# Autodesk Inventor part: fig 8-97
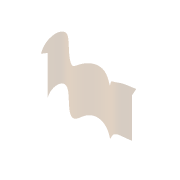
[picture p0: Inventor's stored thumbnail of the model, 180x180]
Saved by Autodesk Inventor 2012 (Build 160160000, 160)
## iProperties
Shininess: 64.0
Length Units: 11269
Angle Units: 11279
Time Units: 11290
Mass Units: 11283
Length Display Precision: 3
Angle Display Precision: 2
Compacted: True
Part Number: fig 8-97
Document SubType Name: Modeling
Created: 2003-08
Designer: Owner
Manufacturer: Standard
Standards Organization: Custom
Density: 1 g/cm^3
Material: Default
Density: 0.0
Volumn: 0.0
Area: 0.0
PropertySet Name: Model Information
Control State: 0
Master: False
Checked Out: False
Author: Owner
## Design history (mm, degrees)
sketch "Sketch1"
  geometry: 7 further points
  constraints: 7 other
  dimensions: "d0" = 80 horizontal distance of point (40, 1.742) point (-40, -4.065); "d1" = 40 horizontal distance of point (0, 0) point (-40, -4.065)
extrude_surface "ExtrusionSrf1" sketch "Sketch1" dims "d2" = 80, "d3" = 0
sketch "Sketch2"
  geometry: L1 (40, 0)-(40, -40) reference; L2 (-40, 0)-(-40, -40) reference; 7 further points
  constraints: 2 point on line, 7 other
extrude_surface "ExtrusionSrf2" dims "d4" = 80, "d5" = 0
split "Split6"
sketch "3D Sketch1"
feature "SweepSrf1" sketch "3D Sketch1" dims "d6" = 0
feature "Extend1" dims "d7" = 10
body "Srf1"
body "Srf2"
body "Srf3"
node "3D Intersection1"
